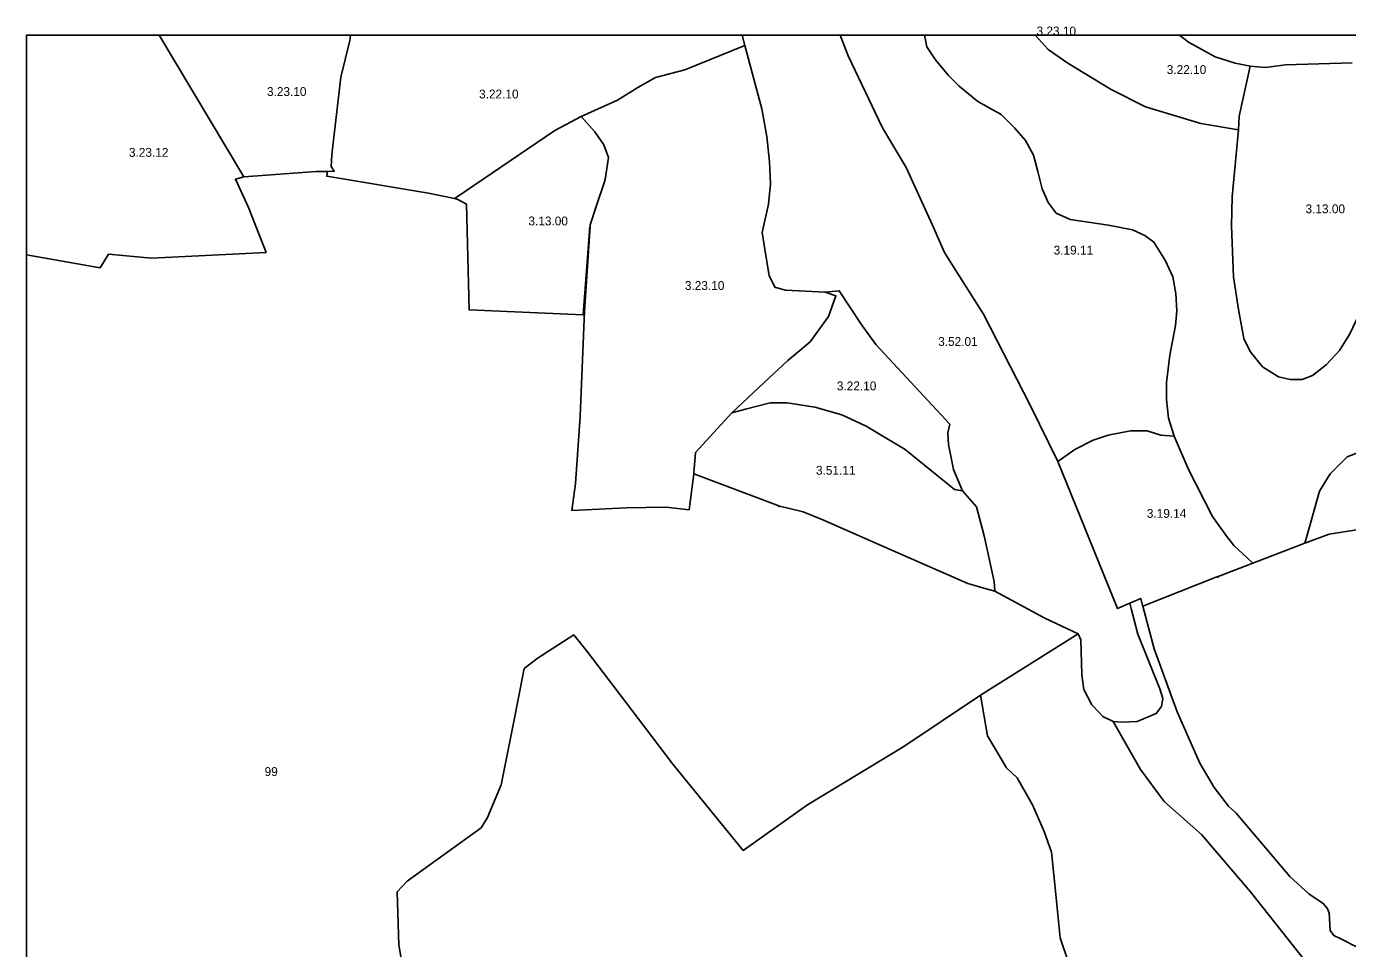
# Model space of a CAD drawing. Extents: x -662500 to -653478, y -1056827 to -1049993.
# Drawn here: x -662500 to -661381, y -1050774 to -1049993 of the extents above; entities that cross this region are included whole.
import ezdxf

# ---------------------------------------------------------------- set-up
doc = ezdxf.new("R2010")
doc.units = 0
doc.layers.add('Vrstva 24', color=7, linetype='Continuous')

msp = doc.modelspace()

# ---------------------------------------------------------------- linework, layer by layer
at = {"layer": 'Vrstva 24'}
for points in [[(-662500, -1050186), (-662500, -1050000), (-662387.5, -1050000)], [(-662387.5, -1050000), (-662225.5, -1050000)], [(-662316, -1050120), (-662387.5, -1050000)], [(-662245, -1050115.4), (-662239.3, -1050115.3), (-662241.8, -1050111.2), (-662241.5, -1050101), (-662233.7, -1050035.5), (-662226.2, -1050004.6), (-662225.5, -1050000)], [(-662225.5, -1050000), (-661894, -1050000)], [(-661891.5, -1050008.8), (-661942.5, -1050029.4), (-661967.3, -1050035.8), (-661982.2, -1050044.3), (-661999.5, -1050055), (-662030.2, -1050068.8)], [(-661894, -1050000), (-661810.8, -1050000)], [(-661894, -1050000), (-661891.5, -1050008.8)], [(-661891.5, -1050008.8), (-661877.1, -1050062.5), (-661873, -1050085.9), (-661870.8, -1050107.4), (-661870, -1050125.8), (-661871.6, -1050143.1), (-661877, -1050167.1), (-661874.9, -1050179.6), (-661870.9, -1050203.7), (-661866, -1050213.6), (-661865.3, -1050213.8), (-661857.2, -1050216.1), (-661823.6, -1050217.8)], [(-661810.8, -1050000), (-661739.5, -1050000)], [(-661626.6, -1050361.2), (-661650.1, -1050313.3), (-661689.6, -1050236.2), (-661711.4, -1050201.5), (-661722.4, -1050184.2), (-661732.8, -1050160.8), (-661755, -1050112), (-661775.1, -1050078.4), (-661804.2, -1050017.6), (-661810.8, -1050000)], [(-661528, -1050339.5), (-661532.9, -1050324.5), (-661534.6, -1050308.5), (-661534.6, -1050294.2), (-661531.8, -1050271.1), (-661526.8, -1050246), (-661525.7, -1050233.4), (-661526.5, -1050218.8), (-661529.2, -1050204.7), (-661535.3, -1050191.2), (-661545.2, -1050175.3), (-661552.9, -1050169.8), (-661563.2, -1050164.8), (-661583.6, -1050161), (-661616.1, -1050156), (-661627.9, -1050150.8), (-661634.8, -1050141.7), (-661639.8, -1050130.1), (-661643.4, -1050115.5), (-661647.2, -1050101.5), (-661653.8, -1050089.1), (-661663.2, -1050078.4), (-661674.6, -1050067.3), (-661694.2, -1050056.3), (-661710.1, -1050043.1), (-661719.2, -1050034), (-661730.2, -1050020.8), (-661737.4, -1050009.8), (-661739.5, -1050000)], [(-661739.5, -1050000), (-661647.5, -1050000)], [(-661647.5, -1050000), (-661639.6, -1050000)], [(-661647.5, -1050000), (-661645.6, -1050000.4)], [(-661645.6, -1050000.4), (-661639.6, -1050000)], [(-661645.6, -1050000.4), (-661634.7, -1050012), (-661618.2, -1050023.8), (-661581.3, -1050046.1), (-661552.2, -1050060.7), (-661505.4, -1050074.8), (-661473.6, -1050080.3)], [(-661639.6, -1050000), (-661523.5, -1050000)], [(-661523.5, -1050000), (-661108.3, -1050000)], [(-661523.5, -1050000), (-661515.9, -1050005.9), (-661493.3, -1050018.3), (-661476.5, -1050023.8), (-661463.8, -1050026.3)], [(-661473.6, -1050080.3), (-661472.9, -1050068.7), (-661463.8, -1050026.3)], [(-661463.8, -1050026.3), (-661450.6, -1050027.4), (-661433.8, -1050025.2), (-661377.4, -1050023.3)], [(-662137.5, -1050138.4), (-662136.1, -1050137.4), (-662052.5, -1050080.6), (-662030.2, -1050068.8)], [(-662030.2, -1050068.8), (-662018.7, -1050081.8), (-662011, -1050093), (-662007.1, -1050103.5), (-662009.8, -1050122.2), (-662010.8, -1050125), (-662017.1, -1050144.2), (-662022.5, -1050160.5), (-662022.6, -1050161.7)], [(-661356.7, -1050184.1), (-661364.2, -1050213.8), (-661369.1, -1050231.4), (-661379.3, -1050252.9), (-661388.1, -1050267), (-661399.4, -1050279.1), (-661411, -1050288.2), (-661419.5, -1050291.5), (-661429.7, -1050291.5), (-661439.6, -1050289.5), (-661453.1, -1050281), (-661463.8, -1050267.8), (-661469.1, -1050256.8), (-661473.6, -1050232.3), (-661477.7, -1050204.7), (-661479.4, -1050161.5), (-661478.8, -1050137), (-661473.6, -1050080.3)], [(-662500, -1050186), (-662437.5, -1050197), (-662430.5, -1050185.5), (-662394, -1050189), (-662297, -1050184), (-662312, -1050146), (-662323, -1050122), (-662316, -1050120)], [(-662316, -1050120), (-662254.5, -1050115.5), (-662245, -1050115.4)], [(-662245, -1050115.4), (-662245.6, -1050119.5), (-662159.6, -1050133.7), (-662137.5, -1050138.4)], [(-662022.6, -1050161.7), (-662023.2, -1050163.9), (-662023.3, -1050166), (-662028.4, -1050237), (-662125.1, -1050232.7), (-662127.4, -1050143.1), (-662135.1, -1050138.9), (-662135.6, -1050138.8), (-662137.5, -1050138.4)], [(-662022.6, -1050161.7), (-662025.3, -1050204.2), (-662027.3, -1050233.7), (-662031, -1050322.9), (-662035.1, -1050379.7), (-662038.2, -1050402.5), (-661992.2, -1050400.3), (-661958.3, -1050399.8), (-661938.8, -1050402), (-661934.9, -1050371.6)], [(-662500, -1051215.9), (-662500, -1050186)], [(-661902.6, -1050319.9), (-661875.3, -1050294.3), (-661855.2, -1050275.6), (-661848.3, -1050269.8), (-661836.2, -1050259.6), (-661820.8, -1050238.4), (-661814.5, -1050220.8), (-661823.6, -1050217.8)], [(-661707.3, -1050385.9), (-661714.8, -1050367.8), (-661719.2, -1050346.6), (-661719.8, -1050336.7), (-661718.1, -1050329.6), (-661780.8, -1050262.1), (-661793.2, -1050244.8), (-661811.7, -1050216.4), (-661823.6, -1050217.8)], [(-661902.6, -1050319.9), (-661933.3, -1050353.6), (-661933.7, -1050357.5), (-661934.5, -1050367), (-661934.8, -1050370.3), (-661934.9, -1050371.6)], [(-661707.3, -1050385.9), (-661714.2, -1050384.9), (-661718.6, -1050381.2), (-661755.8, -1050350.8), (-661788.8, -1050331.2), (-661809.5, -1050321.6), (-661832.3, -1050315.2), (-661855.8, -1050311.4), (-661870.1, -1050311.4), (-661891.1, -1050316.9), (-661902.6, -1050319.9)], [(-661528, -1050339.5), (-661539.3, -1050338.9), (-661550.8, -1050335.1), (-661564.9, -1050335.1), (-661583.9, -1050338.9), (-661596.6, -1050343.1), (-661612.2, -1050351), (-661626.6, -1050361.2)], [(-661528, -1050339.5), (-661516, -1050367.8), (-661495.6, -1050407.8), (-661483.5, -1050424.6), (-661477.5, -1050432.3), (-661466.1, -1050442.7), (-661461.3, -1050447.2)], [(-661258.5, -1050377.9), (-661263.6, -1050367.8), (-661272.4, -1050358.1), (-661285.1, -1050350.1), (-661300.2, -1050346.6), (-661312.3, -1050346.3), (-661349.2, -1050352.1), (-661369.1, -1050352.3), (-661381.5, -1050357), (-661395.8, -1050371.6), (-661404.9, -1050386.2), (-661415.3, -1050423.4), (-661417.3, -1050430.4)], [(-661565.5, -1050481), (-661576, -1050485.7), (-661626.6, -1050361.2)], [(-661934.9, -1050371.6), (-661862.9, -1050398.6), (-661862.9, -1050398.6), (-661862.9, -1050398.6), (-661862.9, -1050398.7), (-661862.9, -1050398.7), (-661862.9, -1050398.7), (-661862.9, -1050398.8), (-661862.9, -1050398.8), (-661862.9, -1050398.8), (-661862.9, -1050398.9), (-661862.9, -1050398.9), (-661862.9, -1050398.9), (-661862.9, -1050398.9), (-661862.9, -1050399), (-661862.8, -1050399), (-661862.8, -1050399), (-661862.8, -1050399.1), (-661862.8, -1050399.1), (-661862.8, -1050399.1), (-661862.7, -1050399.2), (-661862.7, -1050399.2), (-661862.7, -1050399.2), (-661862.7, -1050399.2), (-661862.6, -1050399.2), (-661862.6, -1050399.2), (-661862.6, -1050399.3), (-661862.5, -1050399.3), (-661862.5, -1050399.3), (-661862.5, -1050399.3), (-661862.4, -1050399.3), (-661862.4, -1050399.3), (-661862.4, -1050399.3), (-661862.3, -1050399.3), (-661862.3, -1050399.3), (-661862.3, -1050399.3), (-661862.3, -1050399.3), (-661862.2, -1050399.2), (-661862.2, -1050399.2), (-661862.2, -1050399.2), (-661862.1, -1050399.2), (-661862.1, -1050399.2), (-661862.1, -1050399.2), (-661862.1, -1050399.1), (-661862, -1050399.1), (-661862, -1050399.1), (-661862, -1050399.1), (-661862, -1050399), (-661862, -1050399), (-661862, -1050399), (-661861.9, -1050398.9), (-661861.9, -1050398.9), (-661842.3, -1050403.7), (-661825.5, -1050410.5), (-661778.2, -1050431.3), (-661702.8, -1050464.5), (-661696.7, -1050466.2), (-661696.1, -1050466.3), (-661693, -1050467.2), (-661693, -1050467.2), (-661693, -1050467.2), (-661693, -1050467.3), (-661693, -1050467.3), (-661692.9, -1050467.3), (-661692.9, -1050467.4)], [(-661707.3, -1050385.9), (-661695.5, -1050399.5), (-661688.9, -1050424), (-661680.6, -1050462.8), (-661679.8, -1050470.8)], [(-661298.2, -1050459.6), (-661300.5, -1050454.9), (-661311.1, -1050433.8), (-661314.2, -1050427.5), (-661319.8, -1050419.4), (-661354.2, -1050421.7), (-661358.3, -1050418.4), (-661360.9, -1050416.9), (-661396.8, -1050422.6), (-661417.3, -1050430.4)], [(-661461.3, -1050447.2), (-661417.3, -1050430.4)], [(-661554.7, -1050483.7), (-661491.8, -1050458.8), (-661491.7, -1050458.9), (-661491.7, -1050458.9), (-661491.7, -1050458.9), (-661491.7, -1050458.9), (-661491.7, -1050459), (-661491.6, -1050459), (-661491.6, -1050459), (-661491.6, -1050459), (-661491.6, -1050459.1), (-661491.5, -1050459.1), (-661491.5, -1050459.1), (-661491.5, -1050459.1), (-661491.4, -1050459.1), (-661491.4, -1050459.1), (-661491.4, -1050459.1), (-661491.3, -1050459.1), (-661491.3, -1050459.1), (-661491.3, -1050459.1), (-661491.2, -1050459.1), (-661491.2, -1050459.1), (-661491.2, -1050459.1), (-661491.2, -1050459.1), (-661491.1, -1050459.1), (-661491.1, -1050459.1), (-661491.1, -1050459.1), (-661491, -1050459.1), (-661491, -1050459.1), (-661491, -1050459), (-661491, -1050459), (-661490.9, -1050459), (-661490.9, -1050459), (-661490.9, -1050458.9), (-661490.9, -1050458.9), (-661490.8, -1050458.9), (-661490.8, -1050458.9), (-661490.8, -1050458.8), (-661490.8, -1050458.8), (-661490.8, -1050458.8), (-661490.8, -1050458.7), (-661490.8, -1050458.7), (-661490.8, -1050458.7), (-661490.8, -1050458.6), (-661490.8, -1050458.6), (-661490.8, -1050458.6), (-661490.8, -1050458.6), (-661490.8, -1050458.5), (-661490.8, -1050458.5), (-661490.8, -1050458.5), (-661461.3, -1050447.2)], [(-661692.9, -1050467.4), (-661692.9, -1050467.4), (-661692.9, -1050467.4), (-661692.8, -1050467.4), (-661692.8, -1050467.5), (-661692.8, -1050467.5), (-661692.8, -1050467.5), (-661692.7, -1050467.5), (-661692.7, -1050467.5), (-661692.7, -1050467.5), (-661692.6, -1050467.5), (-661692.6, -1050467.5), (-661692.6, -1050467.5), (-661692.6, -1050467.5), (-661692.5, -1050467.5), (-661692.5, -1050467.5), (-661692.5, -1050467.5), (-661692.4, -1050467.5), (-661692.4, -1050467.5), (-661692.4, -1050467.5), (-661692.3, -1050467.5), (-661692.3, -1050467.5), (-661692.3, -1050467.5), (-661692.3, -1050467.4), (-661692.2, -1050467.4), (-661692.2, -1050467.4), (-661679.8, -1050470.8)], [(-661679.8, -1050470.8), (-661637.7, -1050493.7), (-661609.3, -1050507)], [(-661554.7, -1050483.7), (-661554.8, -1050483.1), (-661556.4, -1050477.1), (-661565.5, -1050481)], [(-661565.5, -1050481), (-661564.1, -1050486.6), (-661558.8, -1050507.4), (-661540.2, -1050553.7), (-661537.7, -1050561.7), (-661538.8, -1050568.6), (-661543.2, -1050574.6), (-661559.5, -1050581.2), (-661572.4, -1050581.8), (-661579.6, -1050581.2)], [(-661373.6, -1050772.3), (-661386.8, -1050765.4), (-661392.9, -1050762.7), (-661395.9, -1050758.3), (-661396.9, -1050743.4), (-661398.5, -1050739.3), (-661401.8, -1050735.4), (-661414, -1050727.4), (-661430.2, -1050712.6), (-661475.5, -1050658.9), (-661482.1, -1050653.1), (-661494.2, -1050637.1), (-661506.3, -1050616.7), (-661525.5, -1050573.2), (-661544.9, -1050519.8), (-661554.7, -1050483.7)], [(-661692, -1050559), (-661757, -1050602.5), (-661838.5, -1050652), (-661893, -1050690.5), (-661952.5, -1050617.5), (-661993.5, -1050563.5), (-662025, -1050522), (-662036.5, -1050508), (-662066.5, -1050527.5), (-662078.5, -1050536.5), (-662086.5, -1050577), (-662098, -1050635), (-662109.5, -1050662.5), (-662115, -1050671.5), (-662177.5, -1050716.5), (-662186, -1050725.5), (-662184.5, -1050770.5), (-662168, -1050869.5), (-662125.5, -1051004.5), (-662116.5, -1051030)], [(-661609.3, -1050507), (-661692, -1050559)], [(-661609.3, -1050507), (-661607.1, -1050512.1), (-661606.3, -1050541.6), (-661606, -1050544), (-661604.6, -1050554.2), (-661597.8, -1050567.2), (-661591, -1050574.3), (-661588.4, -1050577.1), (-661579.6, -1050581.2)], [(-661540, -1051100), (-661539, -1051079.5), (-661559, -1051034.5), (-661562, -1051016.5), (-661558, -1050994), (-661542.5, -1050971.5), (-661533.5, -1050952.5), (-661532.5, -1050931), (-661540.5, -1050908.5), (-661567, -1050866), (-661590, -1050833), (-661617.5, -1050785.5), (-661624.5, -1050764.5), (-661629, -1050719.5), (-661632, -1050692), (-661638, -1050674.5), (-661648, -1050652), (-661661, -1050629), (-661670, -1050620.5), (-661686, -1050593.5), (-661692, -1050559)], [(-661540, -1051100), (-661506.5, -1051065), (-661455, -1051009), (-661422.5, -1050964), (-661405.5, -1050923.5), (-661390, -1050874), (-661389, -1050846.5), (-661393, -1050824), (-661398.5, -1050815.5), (-661411, -1050792), (-661463.5, -1050725.5), (-661505, -1050677), (-661536.5, -1050649), (-661556.5, -1050622), (-661579.6, -1050581.2)]]:
    msp.add_lwpolyline(points, dxfattribs=at)

# ---------------------------------------------------------------- texts
for s, p in [('3.23.10', (-661644.6, -1050000.2)), ('3.22.10', (-661534.3, -1050032.9)), ('3.23.10', (-662296.3, -1050051.5)), ('3.22.10', (-662116.7, -1050053.6)), ('3.23.12', (-662413.2, -1050103)), ('3.13.00', (-662074.9, -1050161.1)), ('3.13.00', (-661416.8, -1050150.8)), ('3.19.11', (-661630.1, -1050185.8)), ('3.23.10', (-661942.4, -1050215.8)), ('3.52.01', (-661727.9, -1050263.2)), ('3.22.10', (-661813.7, -1050300.8)), ('3.51.11', (-661831.4, -1050372.3)), ('3.19.14', (-661551.2, -1050408.8)), ('99', (-662298.3, -1050627.5))]:
    msp.add_text(s, height=7.5, dxfattribs=at).set_placement(p)

doc.saveas('drawing.dxf')
